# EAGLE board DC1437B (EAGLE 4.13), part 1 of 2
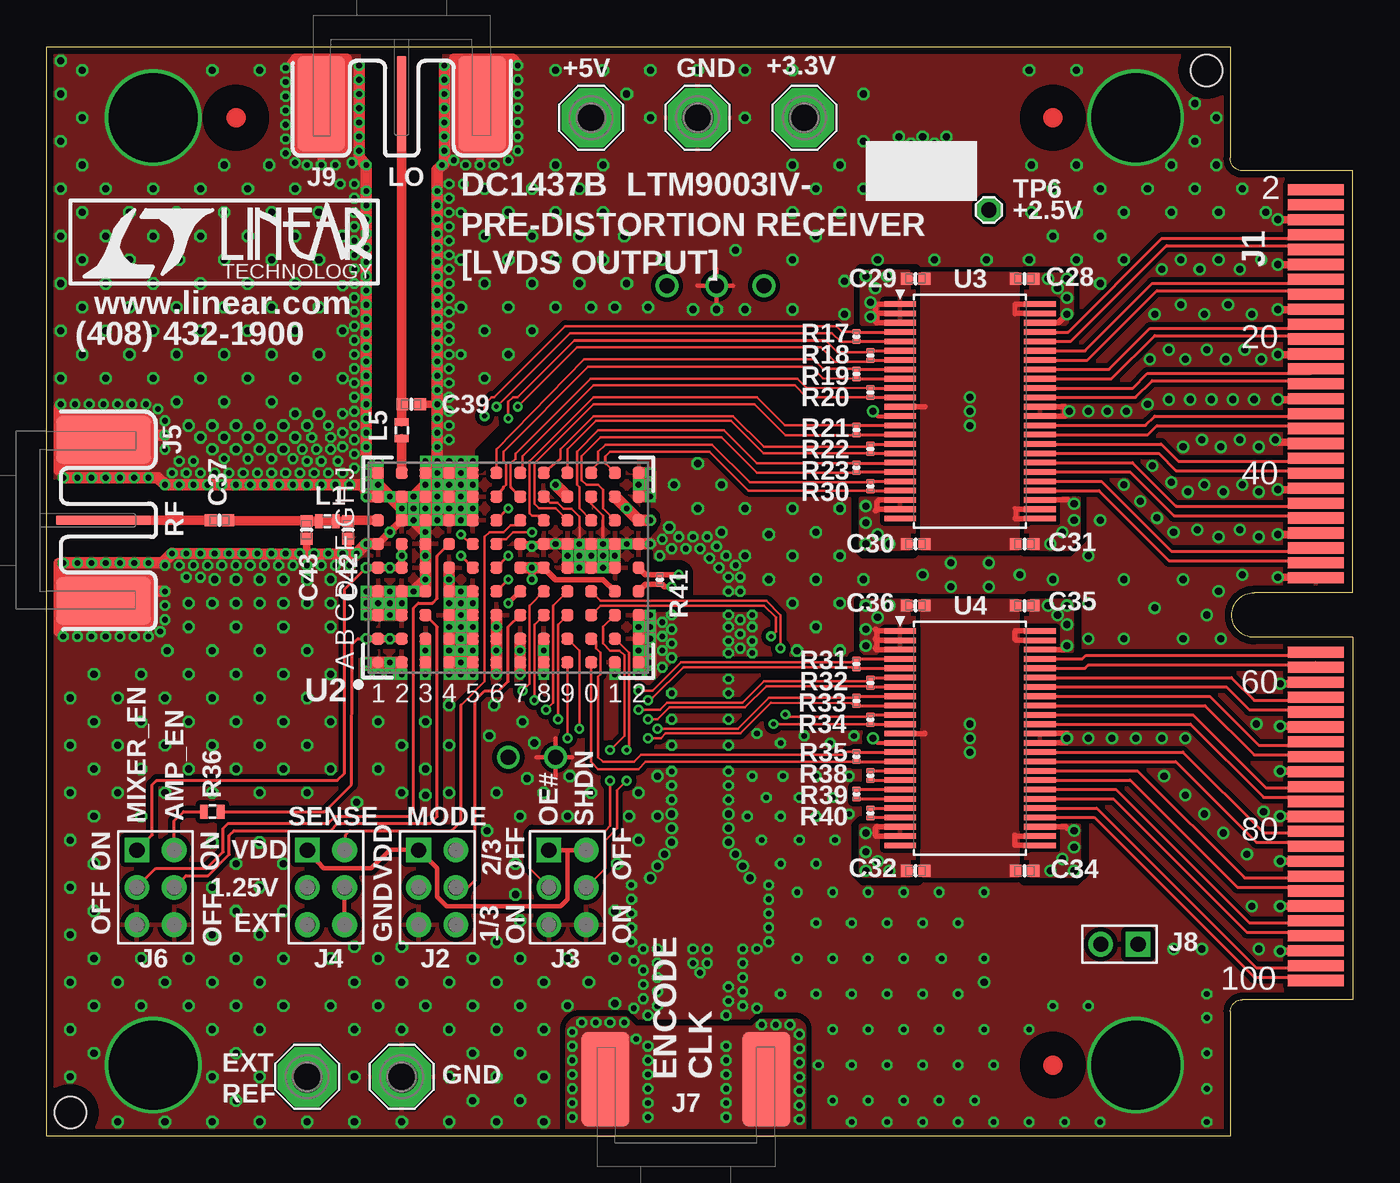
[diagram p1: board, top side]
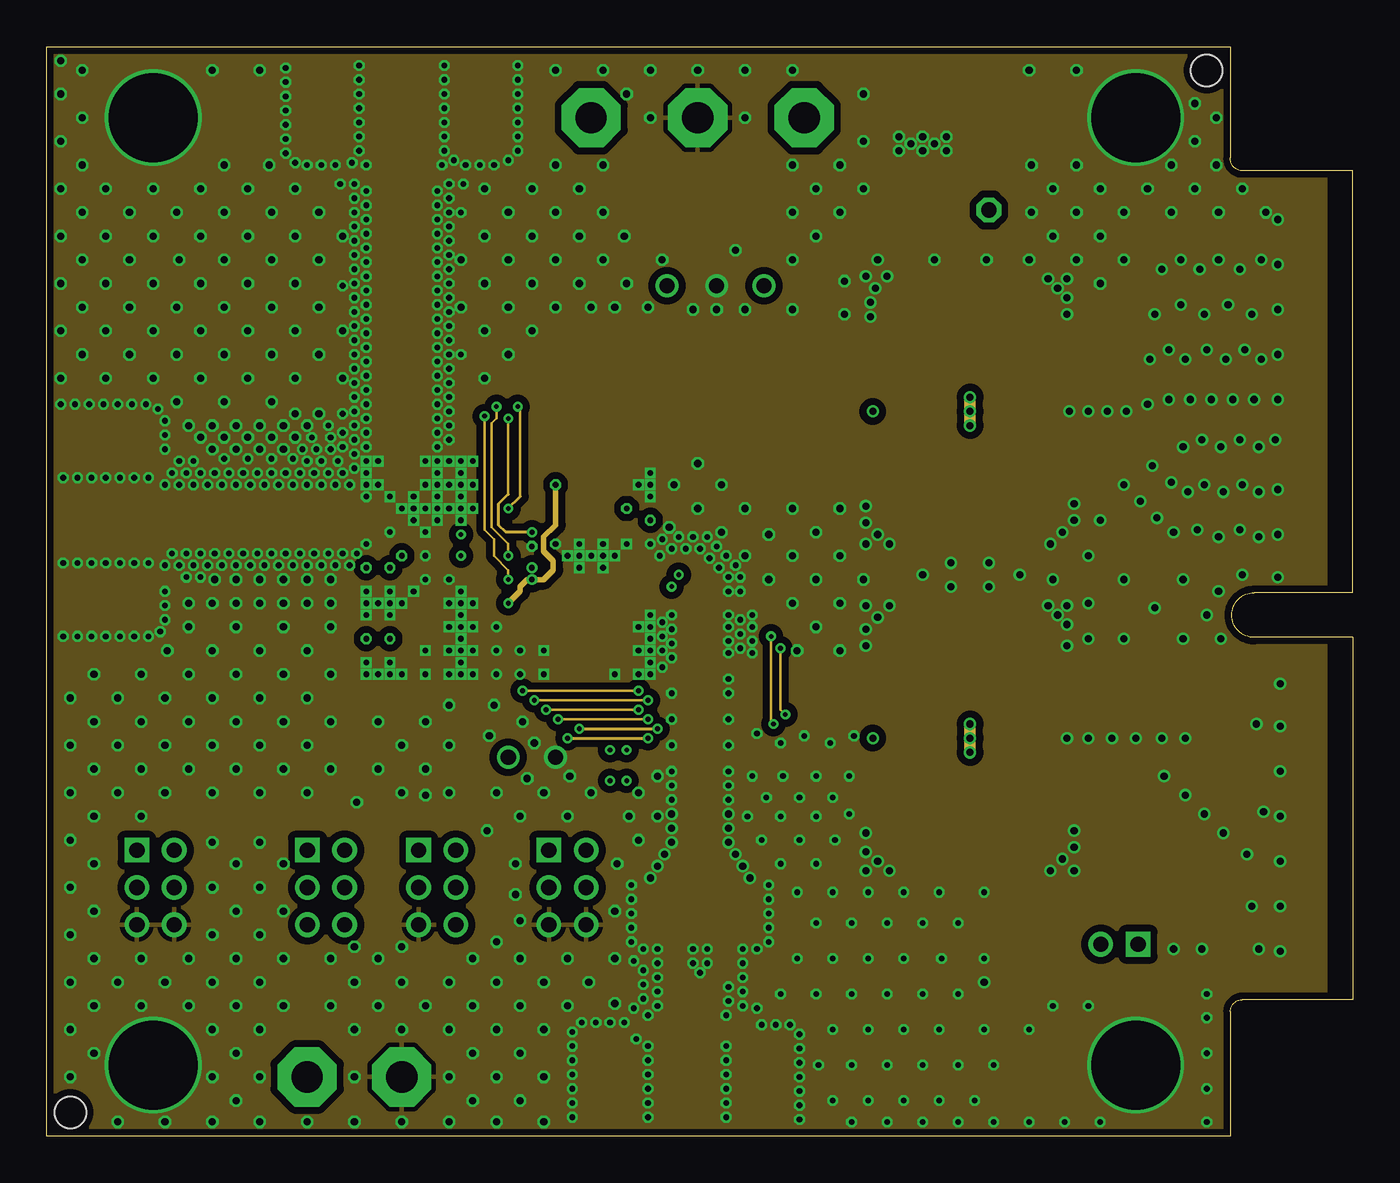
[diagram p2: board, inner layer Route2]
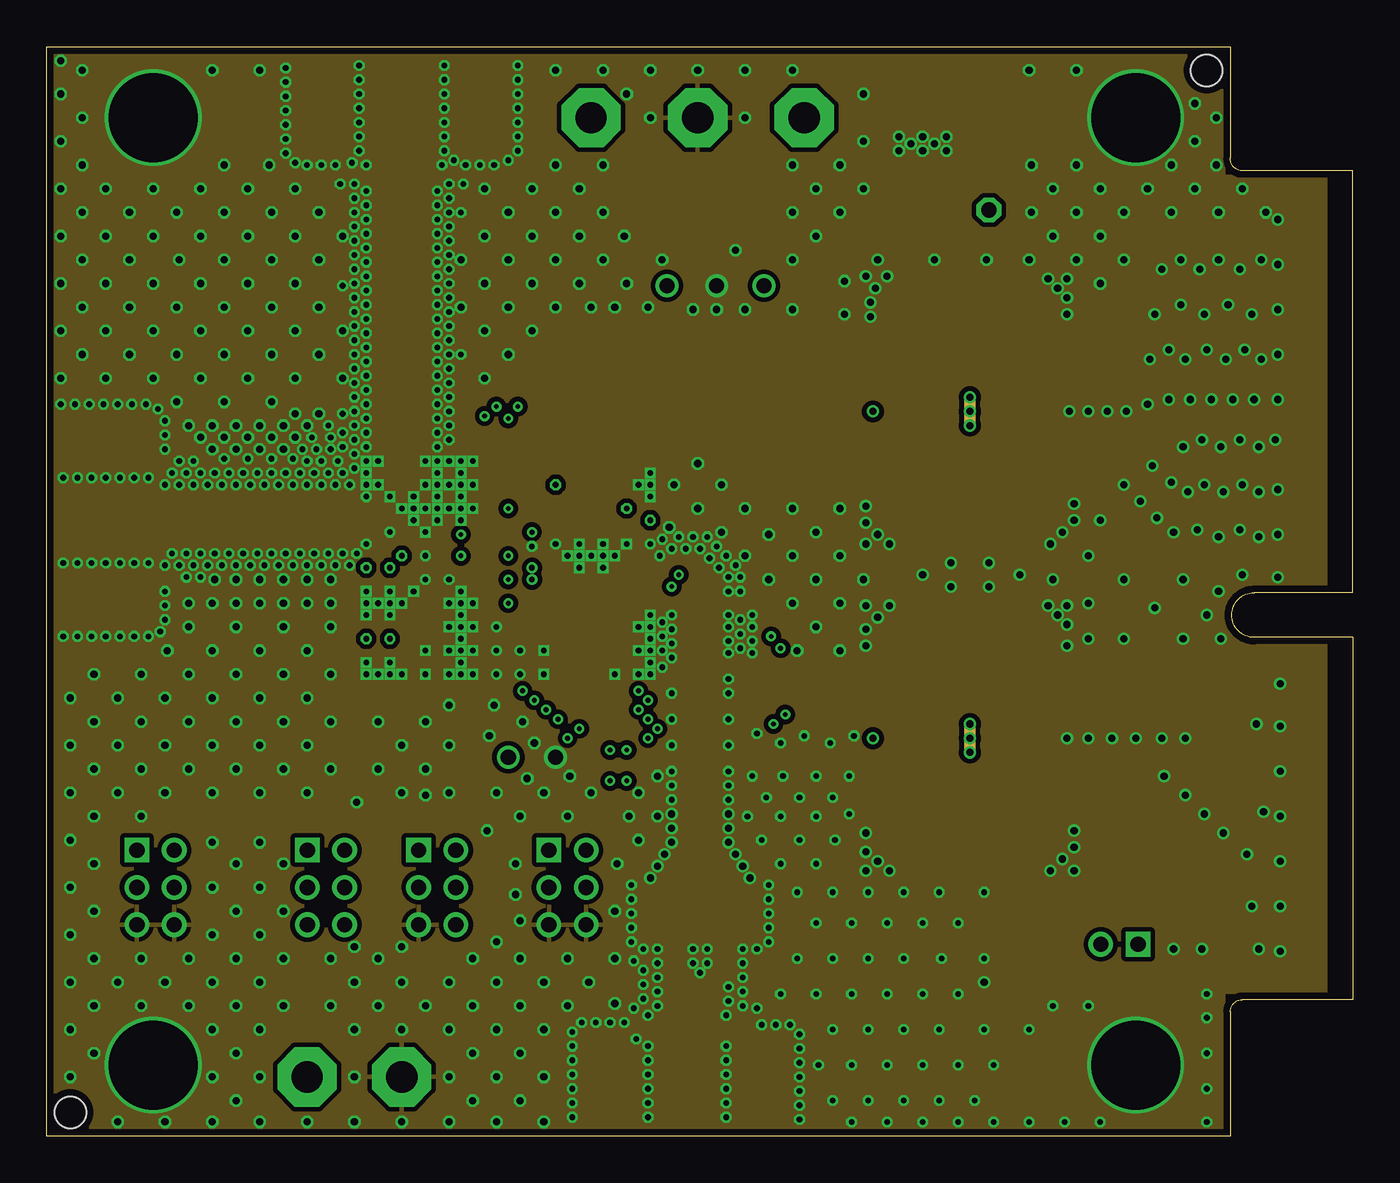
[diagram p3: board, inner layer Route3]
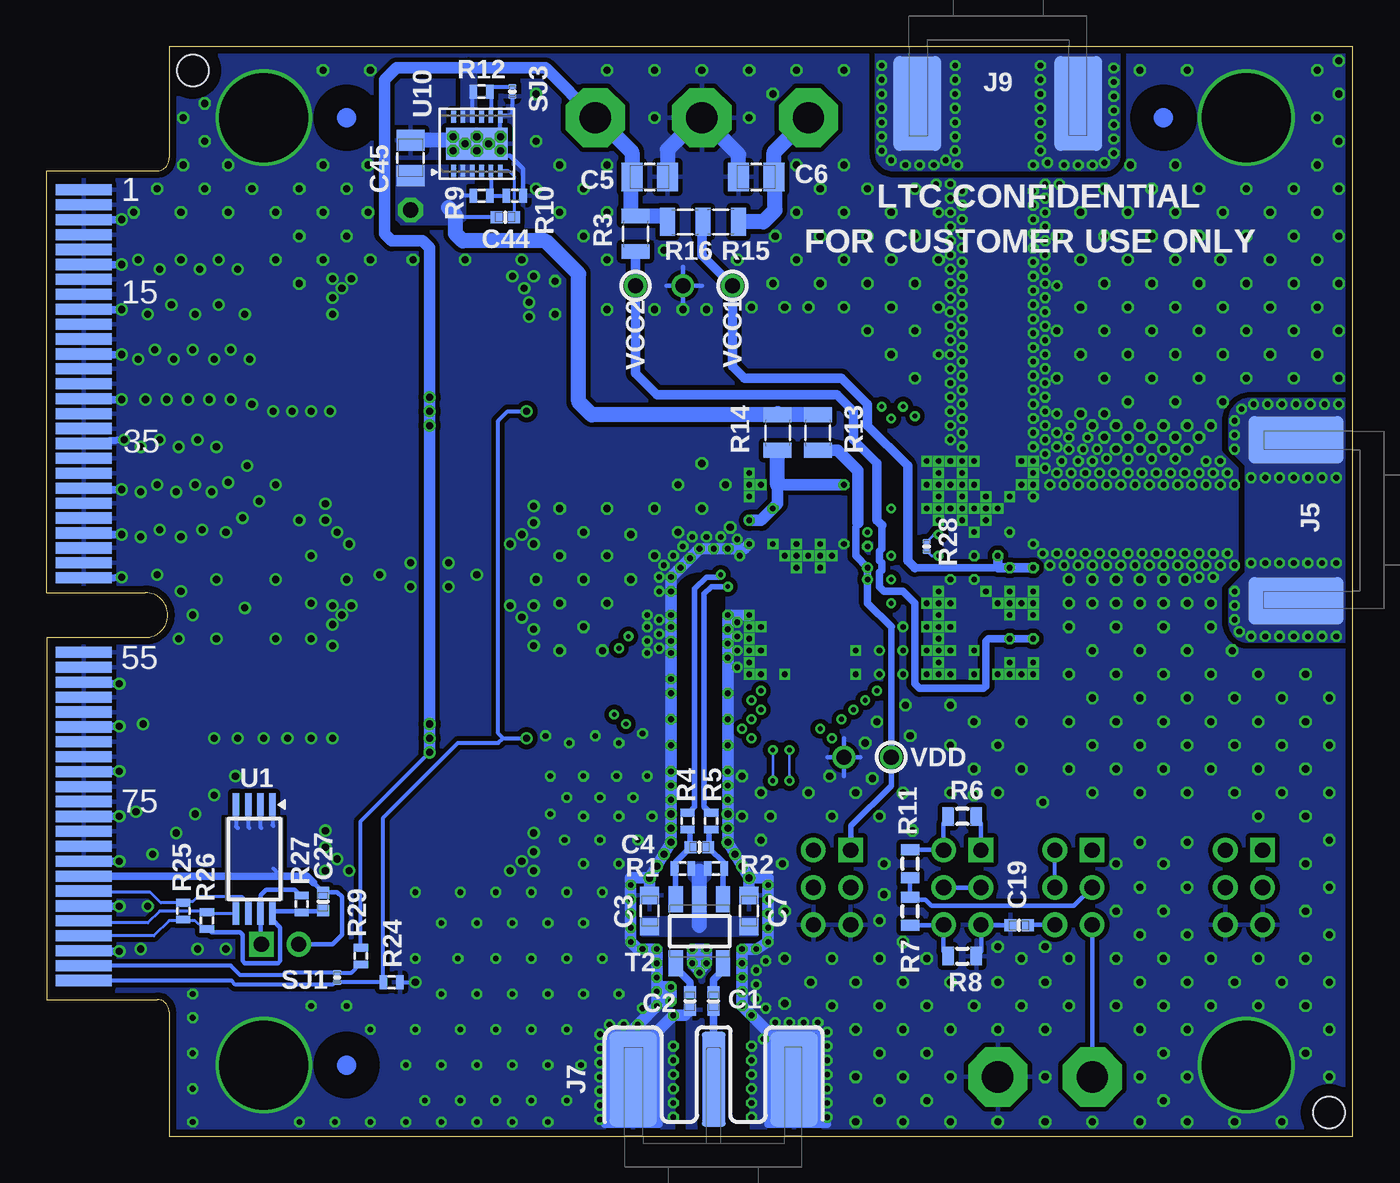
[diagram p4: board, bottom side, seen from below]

Size 70.07 x 58.42 mm. Coordinates in mm from the lower left corner, seen from the top.
Outline: 63.5,6.6 63.5,0 0,0 0,58.42 63.5,58.42 63.5,52.45
Copper layers (1+2*3+16): Top 0.035mm / dielectric 0.28mm / Route2 0.035mm / dielectric 0.7mm / Route3 0.035mm / dielectric 0.28mm / Bottom 0.035mm
Design rules "tight_with_rnding_err_tol": minimum track width 5mil, minimum drill 10mil, track to track 5mil, track to pad 5mil, pad to pad 5mil, via to via 5mil, smd to smd 0mil, copper to edge 15mil, drill to drill 12mil, minimum pad ring 10mil, minimum via ring 0.1372mm, stop-mask expansion 3mil, vias tented up to drill 16mil, thermal gap 10mil
tRestrict: area 35.4,45.1 to 36.5,46.1; area 26.8,19.8 to 27.8,20.8; 96 lines
bRestrict: area 35.4,45.1 to 36.4,46.1; area 26.8,19.8 to 27.8,20.8; 38 lines

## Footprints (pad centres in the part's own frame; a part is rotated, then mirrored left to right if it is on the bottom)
C0402 = smd 0.635 x 0.635: 1 -0.472,0; 2 0.472,0
C0603 = smd 0.914 x 1.016: 1 -0.837,0; 2 0.837,0
C0805 = smd 1.143 x 1.524: 1 -0.952,0; 2 0.952,0
MEC8-150-02-L-D-EDGE_CONN-NEW-ORIGIN = smd 3 x 0.6 bottom: 1 3.3,22.8; 3 3.3,22; 5 3.3,21.2; 7 3.3,20.4; 9 3.3,19.6; 11 3.3,18.8; 13 3.3,18; 15 3.3,17.2; 17 3.3,16.4; 19 3.3,15.6; 21 3.3,14.8; 23 3.3,14; 25 3.3,13.2; 27 3.3,12.4; 29 3.3,11.6; 31 3.3,10.8; 33 3.3,10; 35 3.3,9.2; 37 3.3,8.4; 39 3.3,7.6; 41 3.3,6.8; 43 3.3,6; 45 3.3,5.2; 47 3.3,4.4; 49 3.3,3.6; 51 3.3,2.8; 53 3.3,2; 55 3.3,-2; 57 3.3,-2.8; 59 3.3,-3.6; 61 3.3,-4.4; 63 3.3,-5.2; 65 3.3,-6; 67 3.3,-6.8; 69 3.3,-7.6; 71 3.3,-8.4; 73 3.3,-9.2; 75 3.3,-10; 77 3.3,-10.8; 79 3.3,-11.6; 81 3.3,-12.4; 83 3.3,-13.2; 85 3.3,-14; 87 3.3,-14.8; 89 3.3,-15.6; 91 3.3,-16.4; 93 3.3,-17.2; 95 3.3,-18; 97 3.3,-18.8; 99 3.3,-19.6 | smd 3 x 0.6: 2 3.3,22.8; 4 3.3,22; 6 3.3,21.2; 8 3.3,20.4; 10 3.3,19.6; 12 3.3,18.8; 14 3.3,18; 16 3.3,17.2; 18 3.3,16.4; 20 3.3,15.6; 22 3.3,14.8; 24 3.3,14; 26 3.3,13.2; 28 3.3,12.4; 30 3.3,11.6; 32 3.3,10.8; 34 3.3,10; 36 3.3,9.2; 38 3.3,8.4; 40 3.3,7.6; 42 3.3,6.8; 44 3.3,6; 46 3.3,5.2; 48 3.3,4.4; 50 3.3,3.6; 52 3.3,2.8; 54 3.3,2; 56 3.3,-2; 58 3.3,-2.8; 60 3.3,-3.6; 62 3.3,-4.4; 64 3.3,-5.2; 66 3.3,-6; 68 3.3,-6.8; 70 3.3,-7.6; 72 3.3,-8.4; 74 3.3,-9.2; 76 3.3,-10; 78 3.3,-10.8; 80 3.3,-11.6; 82 3.3,-12.4; 84 3.3,-13.2; 86 3.3,-14; 88 3.3,-14.8; 90 3.3,-15.6; 92 3.3,-16.4; 94 3.3,-17.2; 96 3.3,-18; 98 3.3,-18.8; 100 3.3,-19.6
HDR-3X2PS-2MM = drill 0.813 square: 1 -2,-1 | drill 0.813 round: 2 -2,1; 3 0,-1; 4 0,1; 5 2,-1; 6 2,1
SMA_FEMALE_EDGE_MNT_GHZ = smd 5.08 x 0.508: 1 3.048,0 | smd 5.08 x 2.54: 2 3.048,4.318; 3 3.048,-4.318 | smd 5.08 x 2.54 bottom: 4 3.048,4.318; 5 3.048,-4.318
SMA-FEMALE-EDGE-MNT = smd 5.08 x 1.27: 1 3.048,0 | smd 5.08 x 2.54: 2 3.048,4.318; 3 3.048,-4.318 | smd 5.08 x 2.54 bottom: 4 3.048,4.318; 5 3.048,-4.318
HDR-2X1PS-2MM = drill 0.813 square: 1 0,0 | drill 0.813 round: 2 2,0
L0402 = smd 0.406 x 0.762: 1 -0.447,0; 2 0.447,0
R0402 = smd 0.406 x 0.762: 1 -0.447,0; 2 0.447,0
R0805 = smd 0.8 x 1.5: 1 -0.951,0; 2 0.951,0
R0603 = smd 0.6 x 1: 1 -0.75,0; 2 0.75,0
R0201 = smd 0.279 x 0.432: 1 -0.254,0; 2 0.254,0
SJ1 = smd 0.279 x 0.432: 1 -0.254,0; 2 0.254,0
MACOM_ETC1-XFMR = smd 0.762 x 1.397: 1 0,0; 2 1.27,0; 3 2.54,0; 4 2.54,-3.429; 5 0,-3.429
TURRET_MILLMAX_2308-2 = drill 1.676 pad 3.175 octagon: 1 0,0
VIA-25MIL = drill 0.813 pad 1.143 octagon: 1 0,0
TSSOP8 = smd 0.35 x 1.2: 1 -0.975,-2.925; 2 -0.325,-2.925; 3 0.325,-2.925; 4 0.975,-2.925; 5 0.975,2.925; 6 0.325,2.925; 7 -0.325,2.925; 8 -0.975,2.925
LTM9003-RNDED = smd 0.635 x 0.635: A1 -6.985,-5.08; A2 -5.715,-5.08; A3 -4.445,-5.08; A4 -3.175,-5.08; A5 -1.905,-5.08; A6 -0.635,-5.08; A7 0.635,-5.08; A8 1.905,-5.08; A9 3.175,-5.08; A10 4.445,-5.08; A11 5.715,-5.08; A12 6.985,-5.08; B1 -6.985,-3.81; B2 -5.715,-3.81; B3 -4.445,-3.81; B4 -3.175,-3.81; B5 -1.905,-3.81; B6 -0.635,-3.81; B7 0.635,-3.81; B8 1.905,-3.81; B9 3.175,-3.81; B10 4.445,-3.81; B11 5.715,-3.81; B12 6.985,-3.81; C1 -6.985,-2.54; C2 -5.715,-2.54; C3 -4.445,-2.54; C4 -3.175,-2.54; C5 -1.905,-2.54; C6 -0.635,-2.54; C7 0.635,-2.54; C8 1.905,-2.54; C9 3.175,-2.54; C10 4.445,-2.54; C11 5.715,-2.54; C12 6.985,-2.54; D1 -6.985,-1.27; D2 -5.715,-1.27; D3 -4.445,-1.27; D4 -3.175,-1.27; D5 -1.905,-1.27; D6 -0.635,-1.27; D7 0.635,-1.27; D8 1.905,-1.27; D9 3.175,-1.27; D10 4.445,-1.27; D11 5.715,-1.27; D12 6.985,-1.27; E1 -6.985,0; E2 -5.715,0; E3 -4.445,0; E4 -3.175,0; E5 -1.905,0; E6 -0.635,0; E7 0.635,0; E8 1.905,0; E9 3.175,0; E10 4.445,0; E11 5.715,0; E12 6.985,0; F1 -6.985,1.27; F2 -5.715,1.27; F3 -4.445,1.27; F4 -3.175,1.27; F5 -1.905,1.27; F6 -0.635,1.27; F7 0.635,1.27; F8 1.905,1.27; F9 3.175,1.27; F10 4.445,1.27; F11 5.715,1.27; F12 6.985,1.27; G1 -6.985,2.54; G2 -5.715,2.54; G3 -4.445,2.54; G4 -3.175,2.54; G5 -1.905,2.54; G6 -0.635,2.54; G7 0.635,2.54; G8 1.905,2.54; G9 3.175,2.54; G10 4.445,2.54; G11 5.715,2.54; G12 6.985,2.54; H1 -6.985,3.81; H2 -5.715,3.81; H3 -4.445,3.81; H4 -3.175,3.81; H5 -1.905,3.81; H6 -0.635,3.81; H7 0.635,3.81; H8 1.905,3.81; H9 3.175,3.81; H10 4.445,3.81; H11 5.715,3.81; H12 6.985,3.81; J1 -6.985,5.08; J2 -5.715,5.08; J3 -4.445,5.08; J4 -3.175,5.08; J5 -1.905,5.08; J6 -0.635,5.08; J7 0.635,5.08; J8 1.905,5.08; J9 3.175,5.08; J10 4.445,5.08; J11 5.715,5.08; J12 6.985,5.08
TSSOP48 = smd 0.3 x 1.7: 1 -5.75,-3.75; 2 -5.25,-3.75; 3 -4.75,-3.75; 4 -4.25,-3.75; 5 -3.75,-3.75; 6 -3.25,-3.75; 7 -2.75,-3.75; 8 -2.25,-3.75; 9 -1.75,-3.75; 10 -1.25,-3.75; 11 -0.75,-3.75; 12 -0.25,-3.75; 13 0.25,-3.75; 14 0.75,-3.75; 15 1.25,-3.75; 16 1.75,-3.75; 17 2.25,-3.75; 18 2.75,-3.75; 19 3.25,-3.75; 20 3.75,-3.75; 21 4.25,-3.75; 22 4.75,-3.75; 23 5.25,-3.75; 24 5.75,-3.75; 25 5.75,3.75; 26 5.25,3.75; 27 4.75,3.75; 28 4.25,3.75; 29 3.75,3.75; 30 3.25,3.75; 31 2.75,3.75; 32 2.25,3.75; 33 1.75,3.75; 34 1.25,3.75; 35 0.75,3.75; 36 0.25,3.75; 37 -0.25,3.75; 38 -0.75,3.75; 39 -1.25,3.75; 40 -1.75,3.75; 41 -2.25,3.75; 42 -2.75,3.75; 43 -3.25,3.75; 44 -3.75,3.75; 45 -4.25,3.75; 46 -4.75,3.75; 47 -5.25,3.75; 48 -5.75,3.75
DE12 = smd 0.25 x 0.65: 1 -1.25,-1.45; 2 -0.75,-1.45; 3 -0.25,-1.45; 4 0.25,-1.45; 5 0.75,-1.45; 6 1.25,-1.45; 7 1.25,1.45; 8 0.75,1.45; 9 0.25,1.45; 10 -0.25,1.45; 11 -0.75,1.45; 12 -1.25,1.45 | smd 3.3 x 1.7: GP 0,0
TOOLING_HOLE_0R067 = hole 1.702: 0,0

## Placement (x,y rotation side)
C1  0.01uF  [C0402]  34.29,7.24 90 bottom
C2  0.01uF  [C0402]  35.56,7.24 90 bottom
C3  0.1uF  [C0603]  37.72,12.06 90 bottom
C4  8.2pF  [C0402]  35.05,15.49 0 bottom
C5  4.7uF  [C0805]  37.72,51.44 0 bottom
C6  4.7uF  [C0805]  32,51.44 180 bottom
C7  0.1uF  [C0603]  32.38,12.06 90 bottom
C19  0.1uF  [C0402]  17.91,11.3 180 bottom
C27  0.1uF  [C0402]  55.25,12.57 90 bottom
C28  0.1uF  [C0402]  52.45,45.97 0 top
C29  0.1uF  [C0402]  46.61,45.97 180 top
C30  0.1uF  [C0402]  46.61,31.75 180 top
C31  0.1uF  [C0402]  52.45,31.75 0 top
C32  0.1uF  [C0402]  46.61,14.22 180 top
C34  0.1uF  [C0402]  52.45,14.22 0 top
C35  0.1uF  [C0402]  52.45,28.45 0 top
C36  0.1uF  [C0402]  46.61,28.45 180 top
C37  DNI  [C0402]  9.27,33.02 180 top
C39  DNI  [C0402]  19.56,39.24 0 top
C42  DNI  [C0402]  16.18,32.51 270 top
C43  1pF  [C0402]  13.94,32.51 270 top
C44  0.01uF  [C0402]  45.47,49.28 0 bottom
C45  10uF  [C0805]  50.55,52.45 90 bottom
J1  MEC8-150-02-L-D-EDGE_CONNRE-DIM  [MEC8-150-02-L-D-EDGE_CONN-NEW-ORIGIN]  64.77,27.94 0 top
J2  2802S-06G2  [HDR-3X2PS-2MM]  20.95,13.33 270 top
J3  2802S-06G2  [HDR-3X2PS-2MM]  27.94,13.33 270 top
J4  2802S-06G2  [HDR-3X2PS-2MM]  14.99,13.33 270 top
J5  SMA  [SMA_FEMALE_EDGE_MNT_GHZ]  0,33.02 0 top
J6  2802S-06G2  [HDR-3X2PS-2MM]  5.84,13.33 270 top
J7  SMA  [SMA-FEMALE-EDGE-MNT]  34.29,0 90 bottom
J8  JMPR-2X1-PS-2MM  [HDR-2X1PS-2MM]  58.55,10.29 180 top
J9  SMA  [SMA_FEMALE_EDGE_MNT_GHZ]  19.05,58.42 270 top
L1  3.9nH  [L0402]  15.06,32.97 0 top
L5  2.7nH  [L0402]  19.05,37.85 270 top
R1  49.9  [R0402]  35.94,14.35 0 bottom
R2  49.9  [R0402]  34.16,14.35 180 bottom
R3  0  [R0805]  38.48,48.39 270 bottom
R4  4.99  [R0402]  35.69,16.89 90 bottom
R5  4.99  [R0402]  34.42,16.89 90 bottom
R6  1000  [R0603]  20.95,17.14 180 bottom
R7  499  [R0603]  23.75,12.06 90 bottom
R8  1000  [R0603]  20.95,9.65 0 bottom
R9  64.9K  [R0402]  46.74,50.42 180 bottom
R10  100K  [R0402]  44.96,50.42 180 bottom
R11  499  [R0603]  23.75,14.61 90 bottom
R12  10K  [R0402]  46.74,56.01 180 bottom
R13  0  [R0805]  28.7,37.72 270 bottom
R14  0  [R0805]  30.86,37.72 270 bottom
R15  DNI  [R0805]  33.91,49.02 180 bottom
R16  0  [R0805]  35.81,49.02 0 bottom
R17  100  [R0201]  43.43,42.88 270 top
R18  100  [R0201]  44.2,41.86 270 top
R19  100  [R0201]  43.43,40.87 270 top
R20  100  [R0201]  44.2,39.88 270 top
R21  100  [R0201]  43.43,37.87 270 top
R22  100  [R0201]  44.2,36.86 270 top
R23  100  [R0201]  43.43,35.84 270 top
R24  100K  [R0402]  51.56,8.26 180 bottom
R25  4990  [R0402]  62.74,12.06 270 bottom
R26  4990  [R0402]  61.47,11.56 270 bottom
R27  4990  [R0402]  56.39,12.45 270 bottom
R28  100  [R0201]  22.86,31.62 270 bottom
R29  4990  [R0402]  53.21,9.65 90 bottom
R30  100  [R0201]  44.2,34.85 270 top
R31  100  [R0201]  43.43,25.32 270 top
R32  100  [R0201]  44.2,24.31 270 top
R33  100  [R0201]  43.43,23.34 270 top
R34  100  [R0201]  44.2,22.33 270 top
R35  100  [R0201]  43.43,20.35 270 top
R36  4990  [R0402]  8.89,17.4 0 top
R38  100  [R0201]  44.2,19.33 270 top
R39  100  [R0201]  43.43,18.34 270 top
R40  100  [R0201]  44.2,17.32 270 top
R41  DNI  [R0201]  32.89,29.84 270 top
SJ1  SOLDER_JMPR-1  [SJ1]  54.48,8.51 270 bottom
SJ3  SOLDER_JMPR-1  [SJ1]  45.09,56.01 270 bottom
T2  MABA-007159-000000  [MACOM_ETC1-XFMR]  36.32,12.7 0 bottom
TP1  TURRET0.063  [TURRET_MILLMAX_2308-2]  13.97,3.17 0 top
TP2  TURRET0.063  [TURRET_MILLMAX_2308-2]  19.05,3.17 0 top
TP3  TURRET0.063  [TURRET_MILLMAX_2308-2]  40.64,54.61 180 top
TP4  TURRET0.063  [TURRET_MILLMAX_2308-2]  34.93,54.61 0 top
TP5  TURRET0.063  [TURRET_MILLMAX_2308-2]  29.21,54.61 0 top
TP6  TSTPNT25MIL  [VIA-25MIL]  50.55,49.66 0 top
U1  24LC02ST  [TSSOP8]  58.93,14.86 180 bottom
U2  LTM9003IV-xx  [LTM9003-RNDED]  24.77,30.48 0 top
U3  FIN1108  [TSSOP48]  49.53,38.86 270 top
U4  FIN1108  [TSSOP48]  49.53,21.34 270 top
U10  LT1763CDE  [DE12]  46.99,53.21 0 bottom
U$2  [TOOLING_HOLE_0R067]  62.23,57.15 0 top
U$3  [TOOLING_HOLE_0R067]  1.27,1.27 0 top
U$4  [FIDUCIAL_0R040]  10.16,54.61 0 top
U$5  [FIDUCIAL_0R040]  53.98,54.61 0 top
U$6  [FIDUCIAL_0R040]  53.98,3.81 0 top
U$7  [LT-LOGO]  1.27,45.72 0 top
U$8  [LETTER_L]  not placed on the board
U$9  [REVISION-HISTORY]  not placed on the board
U$10  [ANSI-DOC-FIELD]  not placed on the board
U$11  [STACKUP-4LAYER,1CORE]  not placed on the board
U$12  [FAB-NOTES-AU-THERMAL]  not placed on the board
U$13  [ARTWORK_TITLEBLOCK]  not placed on the board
